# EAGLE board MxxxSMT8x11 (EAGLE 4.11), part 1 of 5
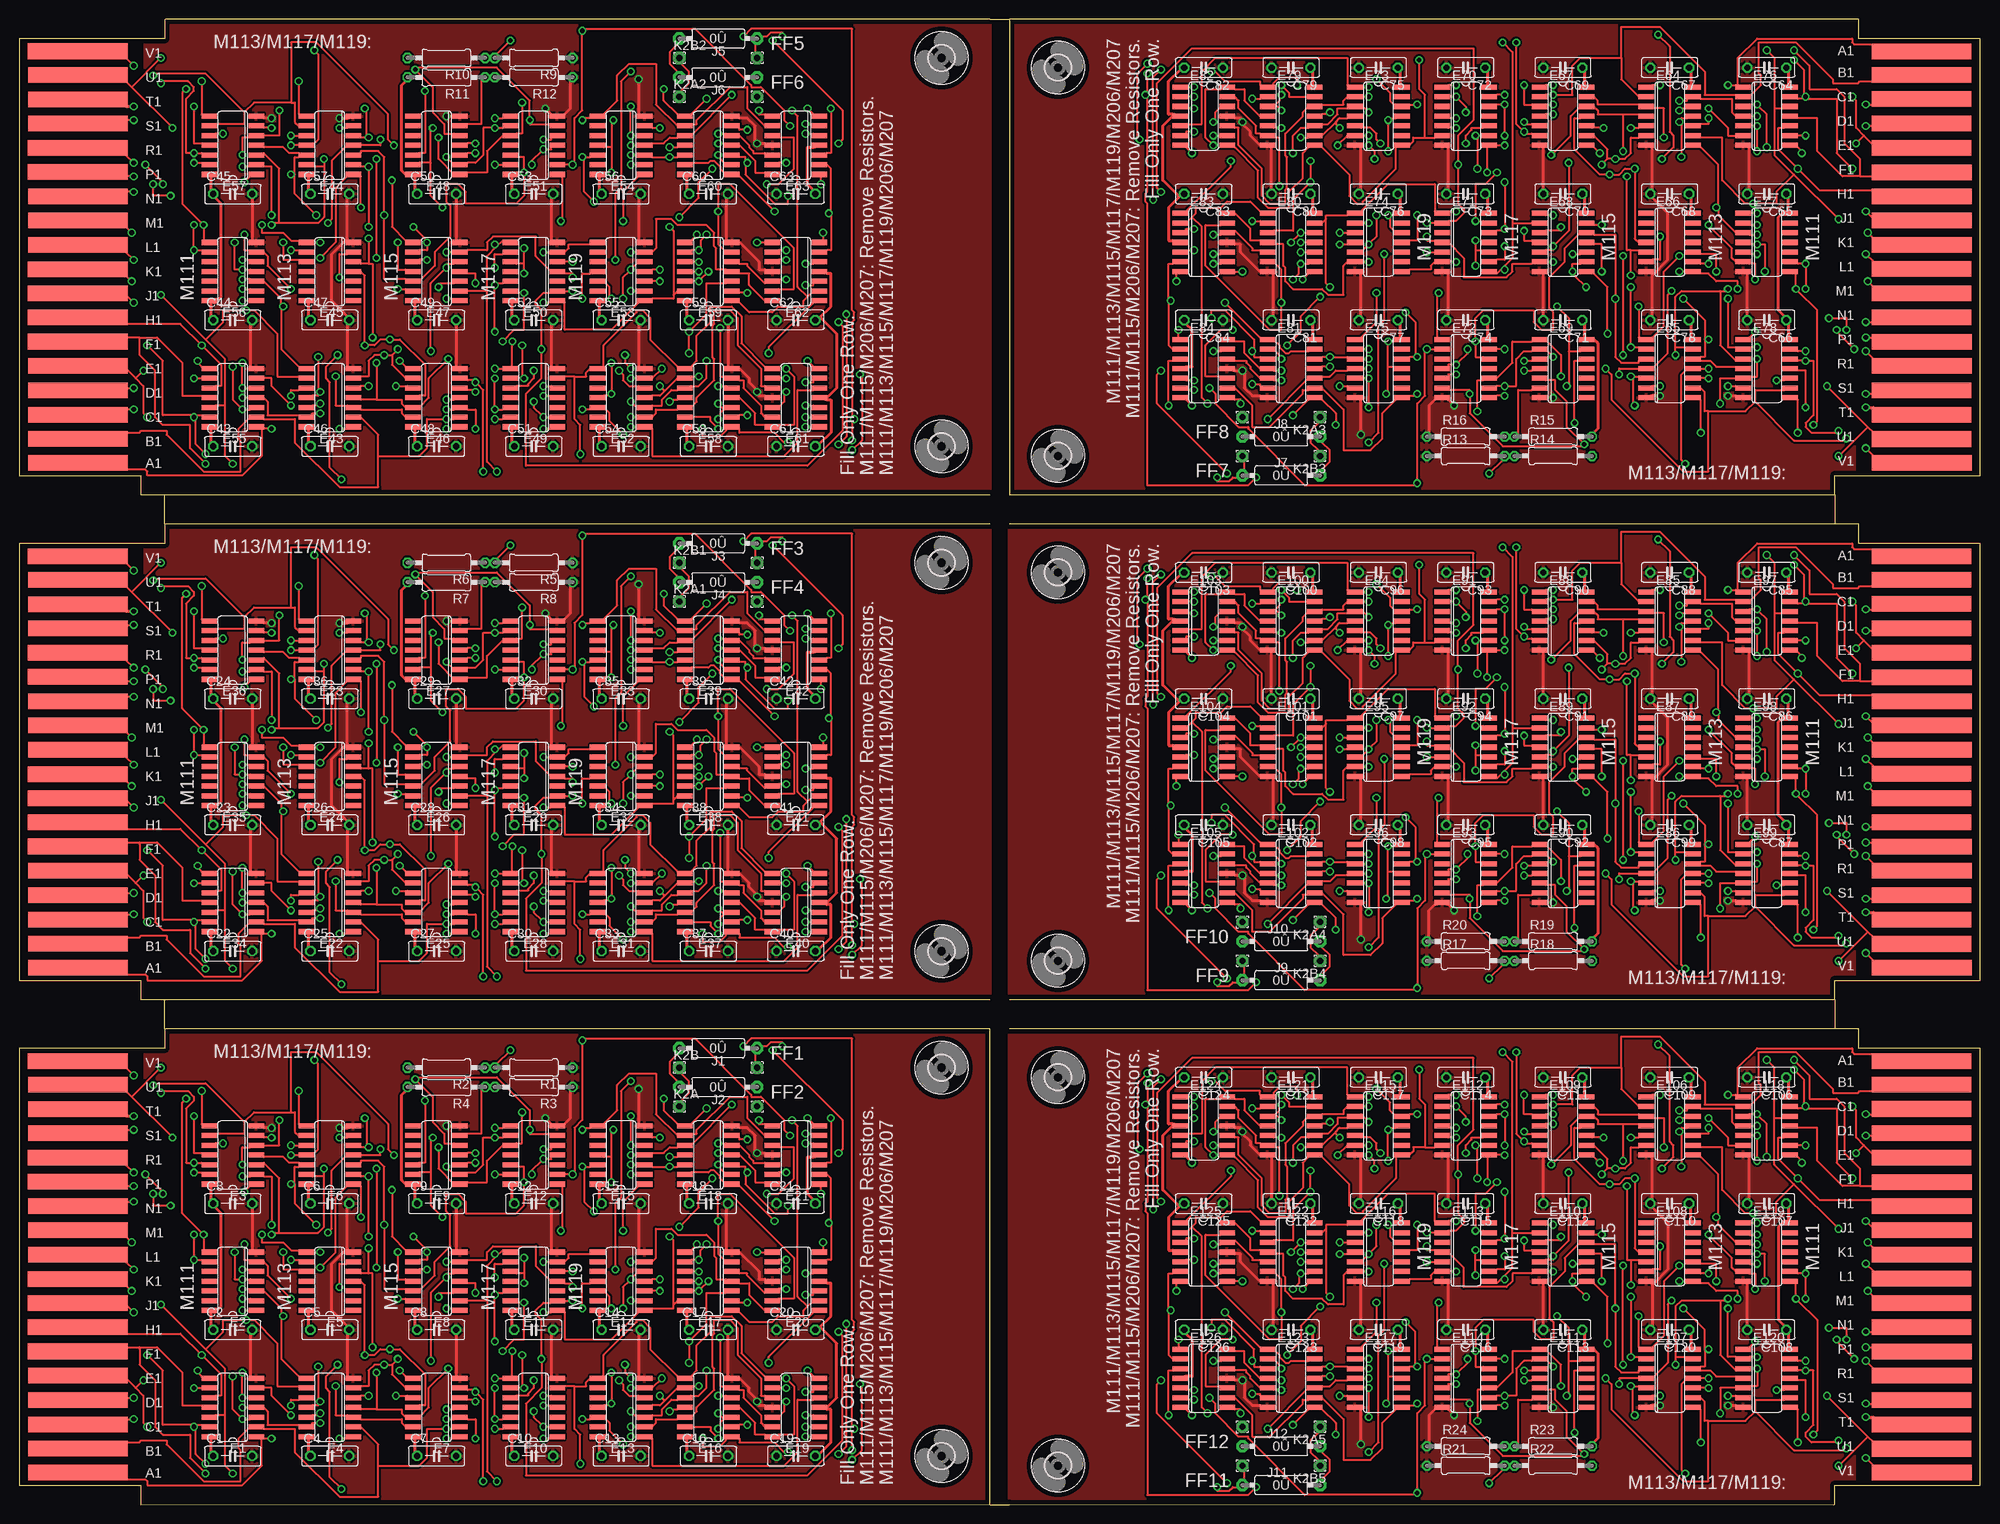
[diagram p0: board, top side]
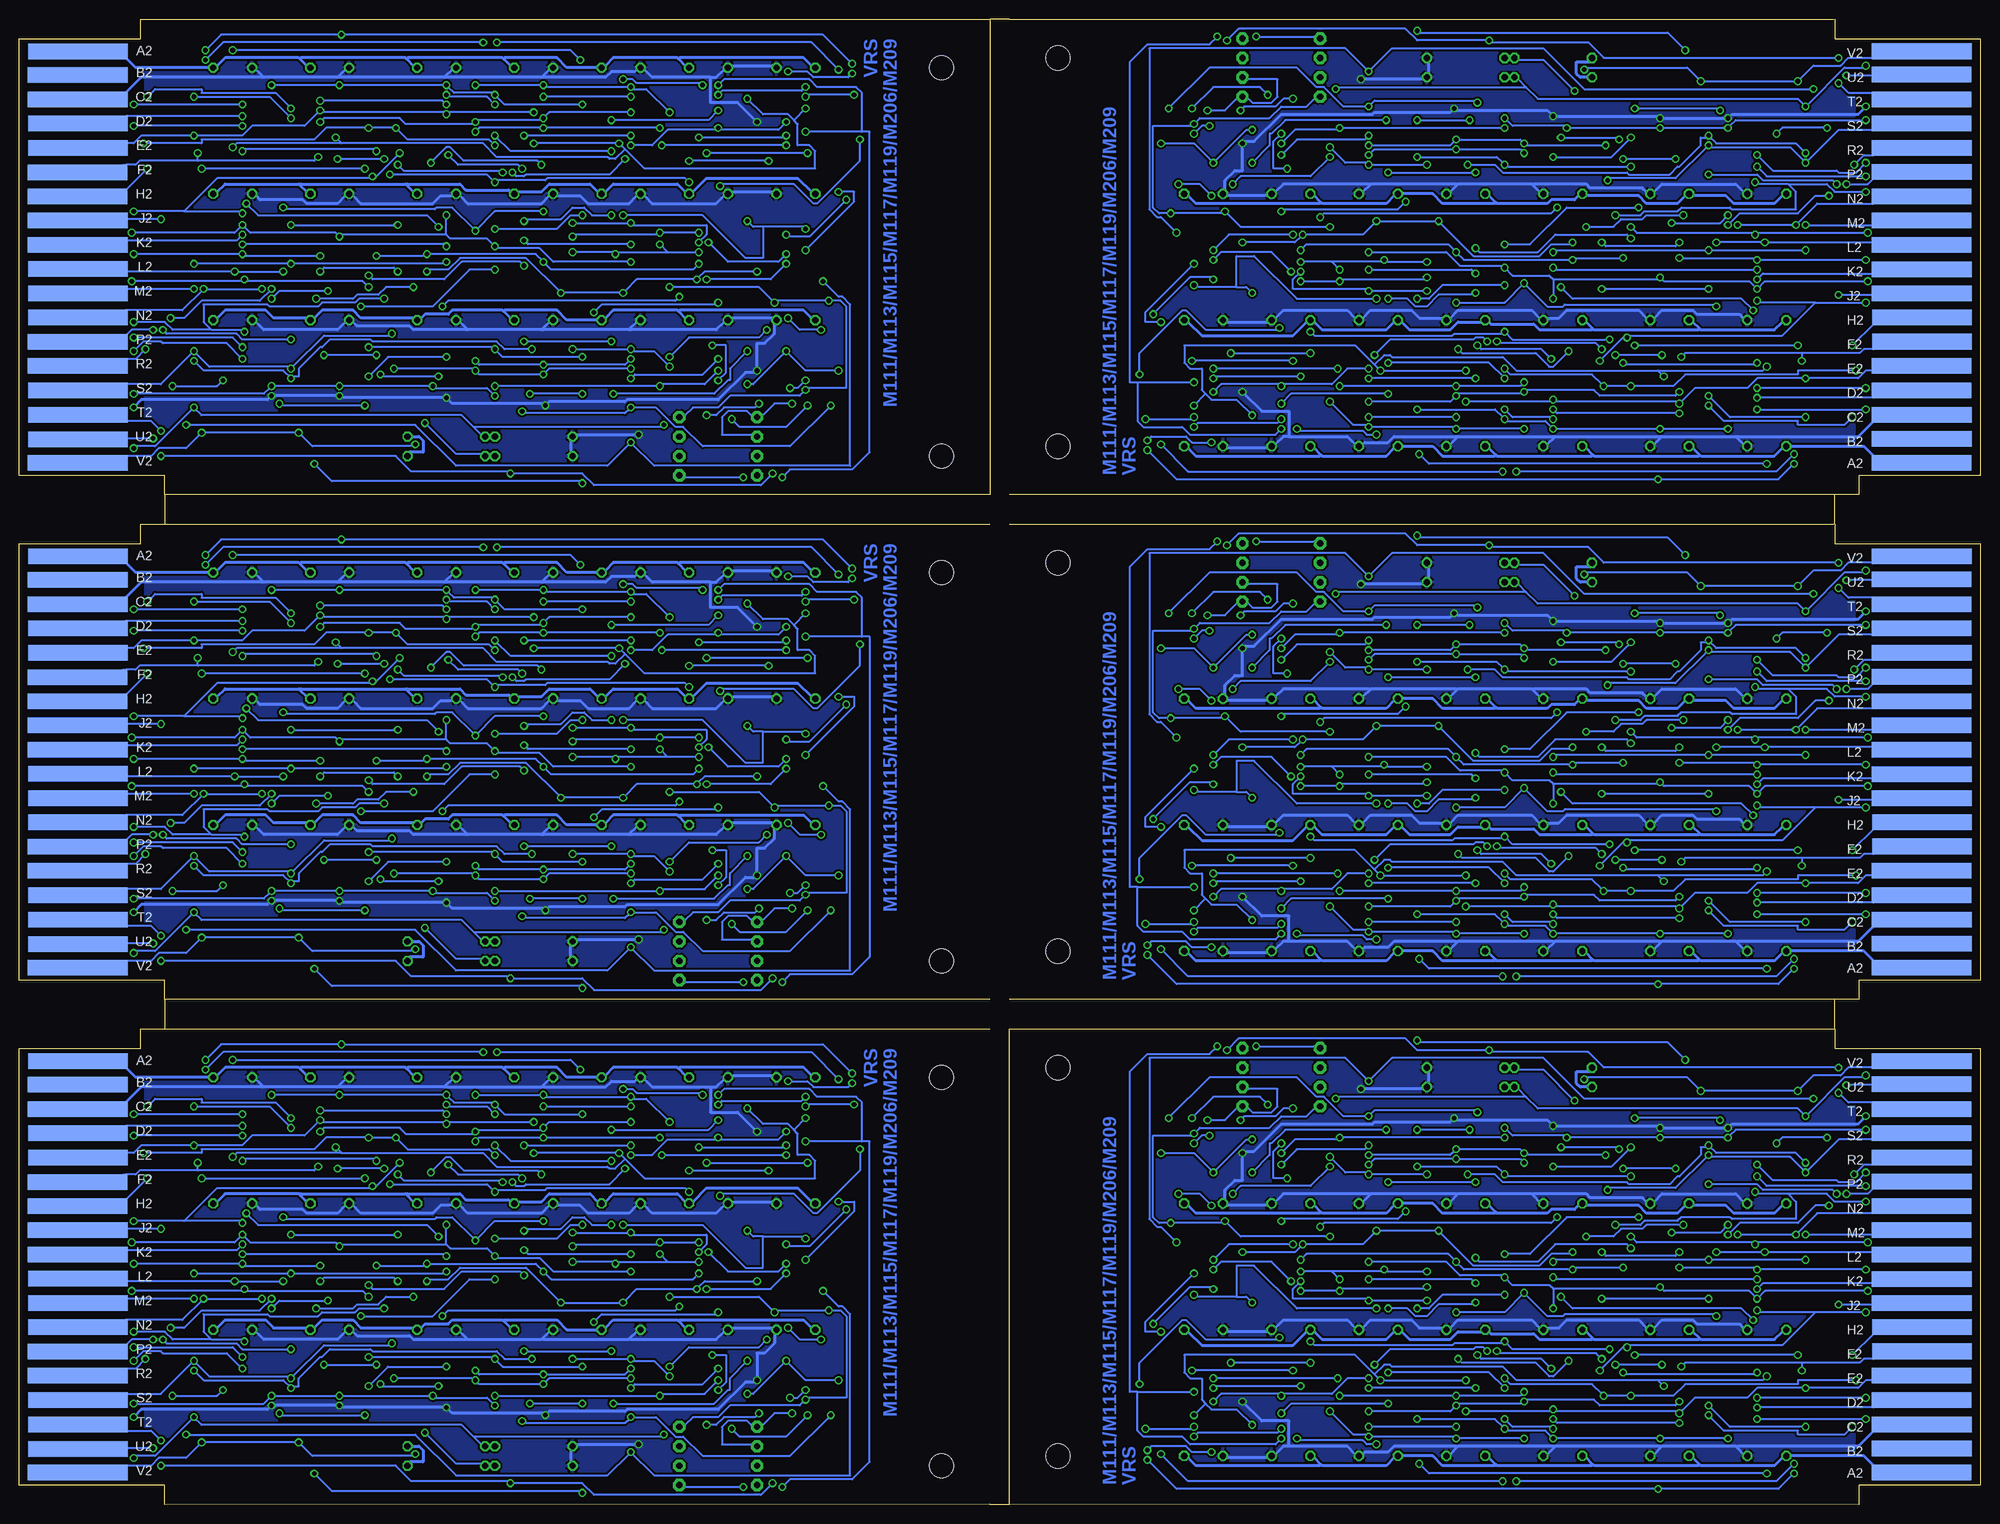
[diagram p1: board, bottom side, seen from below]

Size 256.54 x 194.31 mm. Coordinates in mm from the lower left corner, seen from the top.
Outline: 15.88,0 126.99,0.04 126.99,62.19 19.18,62.23
Outline: 15.88,66.04 126.99,66.08
Outline: 126.99,128.23 19.18,128.27
Outline: 15.88,132.08 126.99,132.12
Outline: 126.99,194.27 19.18,194.31
Outline: 240.67,194.31 129.56,194.27 129.56,132.12 237.36,132.08
Outline: 240.67,128.27 129.56,128.23
Outline: 129.56,66.08 237.36,66.04
Outline: 240.67,62.23 129.56,62.19
Outline: 129.56,0.04 237.36,0
Outline: 127,194.31 129.54,194.31
Outline: 127,0 129.54,0
Outline: 19.05,128.27 19.05,132.08
Outline: 19.05,62.23 19.05,66.04
Outline: 237.49,66.04 237.49,62.23
Outline: 237.49,132.08 237.49,128.27
Copper layers (1*16): Top 0.035mm / dielectric 1.5mm / Bottom 0.035mm
Design rules "olimex10mil": minimum track width 10mil, minimum drill 24mil, track to track 10mil, track to pad 10mil, pad to pad 10mil, via to via 10mil, smd to smd 10mil, copper to edge 25mil, drill to drill 10mil, minimum pad ring 10mil, minimum via ring 8mil, stop-mask expansion 0mil, vias tented up to drill 0mil, thermal gap 10mil
Net classes: 1 Power: width 0.381 mm

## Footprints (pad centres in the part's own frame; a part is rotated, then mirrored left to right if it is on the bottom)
C050-025X075 = drill 0.813 octagon: 1 -2.54,0; 2 2.54,0
SO14 = smd 0.66 x 2.032: 1 -3.81,-3.073; 2 -2.54,-3.073; 3 -1.27,-3.073; 4 0,-3.073; 5 1.27,-3.073; 6 2.54,-3.073; 7 3.81,-3.073; 8 3.81,3.073; 9 2.54,3.073; 10 1.27,3.073; 11 0,3.073; 12 -1.27,3.073; 13 -2.54,3.073; 14 -3.81,3.073
1,6/0,8 = drill 0.813 pad 1.6 octagon: 1 0,0
0R/10 = drill 0.813 pad 1.6 octagon: 1 -5.08,0; 2 5.08,0
0207/10 = drill 0.813 octagon: 1 -5.08,0; 2 5.08,0
EDGE-CON2 = smd 13.017 x 2.032: A1 7.709,4.207; B1 7.684,7.312; C1 7.684,10.474; D1 7.684,13.665; E1 7.693,16.84; F1 7.668,20.041; H1 7.668,23.19; J1 7.668,26.34; K1 7.668,29.515; L1 7.693,32.69; M1 7.693,35.89; N1 7.693,39.04; P1 7.668,42.24; R1 7.668,45.39; S1 7.693,48.565; T1 7.693,51.74; U1 7.693,54.94; V1 7.668,58.026 | smd 13.017 x 2.032 bottom: A2 7.69,4.207; B2 7.668,7.328; C2 7.668,10.49; D2 7.693,13.665; E2 7.693,16.84; F2 7.642,20.041; H2 7.642,23.19; J2 7.668,26.34; K2 7.668,29.515; L2 7.693,32.69; M2 7.693,35.89; N2 7.693,39.04; P2 7.668,42.24; R2 7.668,45.39; S2 7.693,48.565; T2 7.693,51.74; U2 7.693,54.966; V2 7.668,58.026
3,2 = hole 3.2: 0,0

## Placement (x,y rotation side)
C1  0.1uf  [C050-025X075]  27.94,6.35 0 top
C2  0.1uf  [C050-025X075]  27.94,22.86 0 top
C3  0.1uf  [C050-025X075]  27.94,39.37 0 top
C4  0.1uf  [C050-025X075]  40.64,6.35 0 top
C5  0.1uf  [C050-025X075]  40.64,22.86 0 top
C6  0.1uf  [C050-025X075]  40.64,39.37 0 top
C7  0.1uf  [C050-025X075]  54.61,6.35 0 top
C8  0.1uf  [C050-025X075]  54.61,22.86 0 top
C9  0.1uf  [C050-025X075]  54.61,39.37 0 top
C10  0.1uf  [C050-025X075]  67.31,6.35 0 top
C11  0.1uf  [C050-025X075]  67.31,22.86 0 top
C12  0.1uf  [C050-025X075]  67.31,39.37 0 top
C13  0.1uf  [C050-025X075]  78.74,6.35 0 top
C14  0.1uf  [C050-025X075]  78.74,22.86 0 top
C15  0.1uf  [C050-025X075]  78.74,39.37 0 top
C16  0.1uf  [C050-025X075]  90.17,6.35 0 top
C17  0.1uf  [C050-025X075]  90.17,22.86 0 top
C18  0.1uf  [C050-025X075]  90.17,39.37 0 top
C19  0.1uf  [C050-025X075]  101.6,6.35 180 top
C20  0.1uf  [C050-025X075]  101.6,22.86 180 top
C21  0.1uf  [C050-025X075]  101.6,39.37 180 top
C22  0.1uf  [C050-025X075]  27.94,72.39 0 top
C23  0.1uf  [C050-025X075]  27.94,88.9 0 top
C24  0.1uf  [C050-025X075]  27.94,105.41 0 top
C25  0.1uf  [C050-025X075]  40.64,72.39 0 top
C26  0.1uf  [C050-025X075]  40.64,88.9 0 top
C27  0.1uf  [C050-025X075]  54.61,72.39 0 top
C28  0.1uf  [C050-025X075]  54.61,88.9 0 top
C29  0.1uf  [C050-025X075]  54.61,105.41 0 top
C30  0.1uf  [C050-025X075]  67.31,72.39 0 top
C31  0.1uf  [C050-025X075]  67.31,88.9 0 top
C32  0.1uf  [C050-025X075]  67.31,105.41 0 top
C33  0.1uf  [C050-025X075]  78.74,72.39 0 top
C34  0.1uf  [C050-025X075]  78.74,88.9 0 top
C35  0.1uf  [C050-025X075]  78.74,105.41 0 top
C36  0.1uf  [C050-025X075]  40.64,105.41 0 top
C37  0.1uf  [C050-025X075]  90.17,72.39 0 top
C38  0.1uf  [C050-025X075]  90.17,88.9 0 top
C39  0.1uf  [C050-025X075]  90.17,105.41 0 top
C40  0.1uf  [C050-025X075]  101.6,72.39 180 top
C41  0.1uf  [C050-025X075]  101.6,88.9 180 top
C42  0.1uf  [C050-025X075]  101.6,105.41 180 top
C43  0.1uf  [C050-025X075]  27.94,138.43 0 top
C44  0.1uf  [C050-025X075]  27.94,154.94 0 top
C45  0.1uf  [C050-025X075]  27.94,171.45 0 top
C46  0.1uf  [C050-025X075]  40.64,138.43 0 top
C47  0.1uf  [C050-025X075]  40.64,154.94 0 top
C48  0.1uf  [C050-025X075]  54.61,138.43 0 top
C49  0.1uf  [C050-025X075]  54.61,154.94 0 top
C50  0.1uf  [C050-025X075]  54.61,171.45 0 top
C51  0.1uf  [C050-025X075]  67.31,138.43 0 top
C52  0.1uf  [C050-025X075]  67.31,154.94 0 top
C53  0.1uf  [C050-025X075]  67.31,171.45 0 top
C54  0.1uf  [C050-025X075]  78.74,138.43 0 top
C55  0.1uf  [C050-025X075]  78.74,154.94 0 top
C56  0.1uf  [C050-025X075]  78.74,171.45 0 top
C57  0.1uf  [C050-025X075]  40.64,171.45 0 top
C58  0.1uf  [C050-025X075]  90.17,138.43 0 top
C59  0.1uf  [C050-025X075]  90.17,154.94 0 top
C60  0.1uf  [C050-025X075]  90.17,171.45 0 top
C61  0.1uf  [C050-025X075]  101.6,138.43 180 top
C62  0.1uf  [C050-025X075]  101.6,154.94 180 top
C63  0.1uf  [C050-025X075]  101.6,171.45 180 top
C64  0.1uf  [C050-025X075]  228.6,187.96 180 top
C65  0.1uf  [C050-025X075]  228.6,171.45 180 top
C66  0.1uf  [C050-025X075]  228.6,154.94 180 top
C67  0.1uf  [C050-025X075]  215.9,187.96 180 top
C68  0.1uf  [C050-025X075]  215.9,171.45 180 top
C69  0.1uf  [C050-025X075]  201.93,187.96 180 top
C70  0.1uf  [C050-025X075]  201.93,171.45 180 top
C71  0.1uf  [C050-025X075]  201.93,154.94 180 top
C72  0.1uf  [C050-025X075]  189.23,187.96 180 top
C73  0.1uf  [C050-025X075]  189.23,171.45 180 top
C74  0.1uf  [C050-025X075]  189.23,154.94 180 top
C75  0.1uf  [C050-025X075]  177.8,187.96 180 top
C76  0.1uf  [C050-025X075]  177.8,171.45 180 top
C77  0.1uf  [C050-025X075]  177.8,154.94 180 top
C78  0.1uf  [C050-025X075]  215.9,154.94 180 top
C79  0.1uf  [C050-025X075]  166.37,187.96 180 top
C80  0.1uf  [C050-025X075]  166.37,171.45 180 top
C81  0.1uf  [C050-025X075]  166.37,154.94 180 top
C82  0.1uf  [C050-025X075]  154.94,187.96 0 top
C83  0.1uf  [C050-025X075]  154.94,171.45 0 top
C84  0.1uf  [C050-025X075]  154.94,154.94 0 top
C85  0.1uf  [C050-025X075]  228.6,121.92 180 top
C86  0.1uf  [C050-025X075]  228.6,105.41 180 top
C87  0.1uf  [C050-025X075]  228.6,88.9 180 top
C88  0.1uf  [C050-025X075]  215.9,121.92 180 top
C89  0.1uf  [C050-025X075]  215.9,105.41 180 top
C90  0.1uf  [C050-025X075]  201.93,121.92 180 top
C91  0.1uf  [C050-025X075]  201.93,105.41 180 top
C92  0.1uf  [C050-025X075]  201.93,88.9 180 top
C93  0.1uf  [C050-025X075]  189.23,121.92 180 top
C94  0.1uf  [C050-025X075]  189.23,105.41 180 top
C95  0.1uf  [C050-025X075]  189.23,88.9 180 top
C96  0.1uf  [C050-025X075]  177.8,121.92 180 top
C97  0.1uf  [C050-025X075]  177.8,105.41 180 top
C98  0.1uf  [C050-025X075]  177.8,88.9 180 top
C99  0.1uf  [C050-025X075]  215.9,88.9 180 top
C100  0.1uf  [C050-025X075]  166.37,121.92 180 top
C101  0.1uf  [C050-025X075]  166.37,105.41 180 top
C102  0.1uf  [C050-025X075]  166.37,88.9 180 top
C103  0.1uf  [C050-025X075]  154.94,121.92 0 top
C104  0.1uf  [C050-025X075]  154.94,105.41 0 top
C105  0.1uf  [C050-025X075]  154.94,88.9 0 top
C106  0.1uf  [C050-025X075]  228.6,55.88 180 top
C107  0.1uf  [C050-025X075]  228.6,39.37 180 top
C108  0.1uf  [C050-025X075]  228.6,22.86 180 top
C109  0.1uf  [C050-025X075]  215.9,55.88 180 top
C110  0.1uf  [C050-025X075]  215.9,39.37 180 top
C111  0.1uf  [C050-025X075]  201.93,55.88 180 top
C112  0.1uf  [C050-025X075]  201.93,39.37 180 top
C113  0.1uf  [C050-025X075]  201.93,22.86 180 top
C114  0.1uf  [C050-025X075]  189.23,55.88 180 top
C115  0.1uf  [C050-025X075]  189.23,39.37 180 top
C116  0.1uf  [C050-025X075]  189.23,22.86 180 top
C117  0.1uf  [C050-025X075]  177.8,55.88 180 top
C118  0.1uf  [C050-025X075]  177.8,39.37 180 top
C119  0.1uf  [C050-025X075]  177.8,22.86 180 top
C120  0.1uf  [C050-025X075]  215.9,22.86 180 top
C121  0.1uf  [C050-025X075]  166.37,55.88 180 top
C122  0.1uf  [C050-025X075]  166.37,39.37 180 top
C123  0.1uf  [C050-025X075]  166.37,22.86 180 top
C124  0.1uf  [C050-025X075]  154.94,55.88 0 top
C125  0.1uf  [C050-025X075]  154.94,39.37 0 top
C126  0.1uf  [C050-025X075]  154.94,22.86 0 top
E1  7404D  [SO14]  27.94,12.7 90 top
E2  7404D  [SO14]  27.94,29.21 90 top
E3  7404D  [SO14]  27.94,45.72 90 top
E4  7400D  [SO14]  40.64,12.7 90 top
E5  7400D  [SO14]  40.64,29.21 90 top
E6  7400D  [SO14]  40.64,45.72 90 top
E7  7410D  [SO14]  54.61,12.7 90 top
E8  7410D  [SO14]  54.61,29.21 90 top
E9  7410D  [SO14]  54.61,45.72 90 top
E10  7420D  [SO14]  67.31,12.7 90 top
E11  7420D  [SO14]  67.31,29.21 90 top
E12  7420D  [SO14]  67.31,45.72 90 top
E13  7430D  [SO14]  78.74,12.7 90 top
E14  7430D  [SO14]  78.74,29.21 90 top
E15  7430D  [SO14]  78.74,45.72 90 top
E16  7474D  [SO14]  90.17,12.7 90 top
E17  7474D  [SO14]  90.17,29.21 90 top
E18  7474D  [SO14]  90.17,45.72 90 top
E19  7473D  [SO14]  101.6,12.7 90 top
E20  7473D  [SO14]  101.6,29.21 90 top
E21  7473D  [SO14]  101.6,45.72 90 top
E22  7400D  [SO14]  40.64,78.74 90 top
E23  7400D  [SO14]  40.64,111.76 90 top
E24  7400D  [SO14]  40.64,95.25 90 top
E25  7410D  [SO14]  54.61,78.74 90 top
E26  7410D  [SO14]  54.61,95.25 90 top
E27  7410D  [SO14]  54.61,111.76 90 top
E28  7420D  [SO14]  67.31,78.74 90 top
E29  7420D  [SO14]  67.31,95.25 90 top
E30  7420D  [SO14]  67.31,111.76 90 top
E31  7430D  [SO14]  78.74,78.74 90 top
E32  7430D  [SO14]  78.74,95.25 90 top
E33  7430D  [SO14]  78.74,111.76 90 top
E34  7404D  [SO14]  27.94,78.74 90 top
E35  7404D  [SO14]  27.94,95.25 90 top
E36  7404D  [SO14]  27.94,111.76 90 top
E37  7474D  [SO14]  90.17,78.74 90 top
E38  7474D  [SO14]  90.17,95.25 90 top
E39  7474D  [SO14]  90.17,111.76 90 top
E40  7473D  [SO14]  101.6,78.74 90 top
E41  7473D  [SO14]  101.6,95.25 90 top
E42  7473D  [SO14]  101.6,111.76 90 top
E43  7400D  [SO14]  40.64,144.78 90 top
E44  7400D  [SO14]  40.64,177.8 90 top
E45  7400D  [SO14]  40.64,161.29 90 top
E46  7410D  [SO14]  54.61,144.78 90 top
E47  7410D  [SO14]  54.61,161.29 90 top
E48  7410D  [SO14]  54.61,177.8 90 top
E49  7420D  [SO14]  67.31,144.78 90 top
E50  7420D  [SO14]  67.31,161.29 90 top
E51  7420D  [SO14]  67.31,177.8 90 top
E52  7430D  [SO14]  78.74,144.78 90 top
E53  7430D  [SO14]  78.74,161.29 90 top
E54  7430D  [SO14]  78.74,177.8 90 top
E55  7404D  [SO14]  27.94,144.78 90 top
E56  7404D  [SO14]  27.94,161.29 90 top
E57  7404D  [SO14]  27.94,177.8 90 top
E58  7474D  [SO14]  90.17,144.78 90 top
E59  7474D  [SO14]  90.17,161.29 90 top
E60  7474D  [SO14]  90.17,177.8 90 top
E61  7473D  [SO14]  101.6,144.78 90 top
E62  7473D  [SO14]  101.6,161.29 90 top
E63  7473D  [SO14]  101.6,177.8 90 top
E64  7400D  [SO14]  215.9,181.61 270 top
E65  7400D  [SO14]  215.9,148.59 270 top
E66  7400D  [SO14]  215.9,165.1 270 top
E67  7410D  [SO14]  201.93,181.61 270 top
E68  7410D  [SO14]  201.93,165.1 270 top
E69  7410D  [SO14]  201.93,148.59 270 top
E70  7420D  [SO14]  189.23,181.61 270 top
E71  7420D  [SO14]  189.23,165.1 270 top
E72  7420D  [SO14]  189.23,148.59 270 top
E73  7430D  [SO14]  177.8,181.61 270 top
E74  7430D  [SO14]  177.8,165.1 270 top
E75  7430D  [SO14]  177.8,148.59 270 top
E76  7404D  [SO14]  228.6,181.61 270 top
E77  7404D  [SO14]  228.6,165.1 270 top
E78  7404D  [SO14]  228.6,148.59 270 top
E79  7474D  [SO14]  166.37,181.61 270 top
E80  7474D  [SO14]  166.37,165.1 270 top
E81  7474D  [SO14]  166.37,148.59 270 top
E82  7473D  [SO14]  154.94,181.61 270 top
E83  7473D  [SO14]  154.94,165.1 270 top
E84  7473D  [SO14]  154.94,148.59 270 top
E85  7400D  [SO14]  215.9,115.57 270 top
E86  7400D  [SO14]  215.9,82.55 270 top
E87  7400D  [SO14]  215.9,99.06 270 top
E88  7410D  [SO14]  201.93,115.57 270 top
E89  7410D  [SO14]  201.93,99.06 270 top
E90  7410D  [SO14]  201.93,82.55 270 top
E91  7420D  [SO14]  189.23,115.57 270 top
E92  7420D  [SO14]  189.23,99.06 270 top
E93  7420D  [SO14]  189.23,82.55 270 top
E94  7430D  [SO14]  177.8,115.57 270 top
E95  7430D  [SO14]  177.8,99.06 270 top
E96  7430D  [SO14]  177.8,82.55 270 top
E97  7404D  [SO14]  228.6,115.57 270 top
E98  7404D  [SO14]  228.6,99.06 270 top
E99  7404D  [SO14]  228.6,82.55 270 top
E100  7474D  [SO14]  166.37,115.57 270 top
E101  7474D  [SO14]  166.37,99.06 270 top
E102  7474D  [SO14]  166.37,82.55 270 top
E103  7473D  [SO14]  154.94,115.57 270 top
E104  7473D  [SO14]  154.94,99.06 270 top
E105  7473D  [SO14]  154.94,82.55 270 top
E106  7400D  [SO14]  215.9,49.53 270 top
E107  7400D  [SO14]  215.9,16.51 270 top
E108  7400D  [SO14]  215.9,33.02 270 top
E109  7410D  [SO14]  201.93,49.53 270 top
E110  7410D  [SO14]  201.93,33.02 270 top
E111  7410D  [SO14]  201.93,16.51 270 top
E112  7420D  [SO14]  189.23,49.53 270 top
E113  7420D  [SO14]  189.23,33.02 270 top
E114  7420D  [SO14]  189.23,16.51 270 top
E115  7430D  [SO14]  177.8,49.53 270 top
E116  7430D  [SO14]  177.8,33.02 270 top
E117  7430D  [SO14]  177.8,16.51 270 top
E118  7404D  [SO14]  228.6,49.53 270 top
E119  7404D  [SO14]  228.6,33.02 270 top
E120  7404D  [SO14]  228.6,16.51 270 top
E121  7474D  [SO14]  166.37,49.53 270 top
E122  7474D  [SO14]  166.37,33.02 270 top
E123  7474D  [SO14]  166.37,16.51 270 top
E124  7473D  [SO14]  154.94,49.53 270 top
E125  7473D  [SO14]  154.94,33.02 270 top
E126  7473D  [SO14]  154.94,16.51 270 top
FF1  [1,6/0,8]  96.52,57.15 0 top
FF2  [1,6/0,8]  96.52,52.07 0 top
FF3  [1,6/0,8]  96.52,123.19 0 top
FF4  [1,6/0,8]  96.52,118.11 0 top
FF5  [1,6/0,8]  96.52,189.23 0 top
FF6  [1,6/0,8]  96.52,184.15 0 top
FF7  [1,6/0,8]  160.02,137.16 180 top
FF8  [1,6/0,8]  160.02,142.24 180 top
FF9  [1,6/0,8]  160.02,71.12 180 top
FF10  [1,6/0,8]  160.02,76.2 180 top
FF11  [1,6/0,8]  160.02,5.08 180 top
FF12  [1,6/0,8]  160.02,10.16 180 top
J1  [0R/10]  91.44,59.69 0 top
J2  [0R/10]  91.44,54.61 0 top
J3  [0R/10]  91.44,125.73 0 top
J4  [0R/10]  91.44,120.65 0 top
J5  [0R/10]  91.44,191.77 0 top
J6  [0R/10]  91.44,186.69 0 top
J7  [0R/10]  165.1,134.62 180 top
J8  [0R/10]  165.1,139.7 180 top
J9  [0R/10]  165.1,68.58 180 top
J10  [0R/10]  165.1,73.66 180 top
J11  [0R/10]  165.1,2.54 180 top
J12  [0R/10]  165.1,7.62 180 top
K2A  [1,6/0,8]  86.36,52.07 0 top
K2A1  [1,6/0,8]  86.36,118.11 0 top
K2A2  [1,6/0,8]  86.36,184.15 0 top
K2A3  [1,6/0,8]  170.18,142.24 180 top
K2A4  [1,6/0,8]  170.18,76.2 180 top
K2A5  [1,6/0,8]  170.18,10.16 180 top
K2B  [1,6/0,8]  86.36,57.15 0 top
K2B1  [1,6/0,8]  86.36,123.19 0 top
K2B2  [1,6/0,8]  86.36,189.23 0 top
K2B3  [1,6/0,8]  170.18,137.16 180 top
K2B4  [1,6/0,8]  170.18,71.12 180 top
K2B5  [1,6/0,8]  170.18,5.08 180 top
R1  750  [0207/10]  67.31,57.15 180 top
R2  330  [0207/10]  55.88,57.15 180 top
R3  750  [0207/10]  67.31,54.61 180 top
R4  330  [0207/10]  55.88,54.61 180 top
R5  750  [0207/10]  67.31,123.19 180 top
R6  330  [0207/10]  55.88,123.19 180 top
R7  330  [0207/10]  55.88,120.65 180 top
R8  750  [0207/10]  67.31,120.65 180 top
R9  750  [0207/10]  67.31,189.23 180 top
R10  330  [0207/10]  55.88,189.23 180 top
R11  330  [0207/10]  55.88,186.69 180 top
R12  750  [0207/10]  67.31,186.69 180 top
R13  750  [0207/10]  189.23,137.16 0 top
R14  330  [0207/10]  200.66,137.16 0 top
R15  330  [0207/10]  200.66,139.7 0 top
R16  750  [0207/10]  189.23,139.7 0 top
R17  750  [0207/10]  189.23,71.12 0 top
R18  330  [0207/10]  200.66,71.12 0 top
R19  330  [0207/10]  200.66,73.66 0 top
R20  750  [0207/10]  189.23,73.66 0 top
R21  750  [0207/10]  189.23,5.08 0 top
R22  330  [0207/10]  200.66,5.08 0 top
R23  330  [0207/10]  200.66,7.62 0 top
R24  750  [0207/10]  189.23,7.62 0 top
U$1  [EDGE-CON2]  0,0 0 top
U$2  [3,2]  120.65,6.35 0 top
U$3  [3,2]  120.65,57.15 0 top
U$4  [3,2]  120.65,72.39 0 top
U$5  [3,2]  120.65,123.19 0 top
U$6  [EDGE-CON2]  0,66.04 0 top
U$7  [3,2]  120.65,138.43 0 top
U$8  [3,2]  120.65,189.23 0 top
U$9  [EDGE-CON2]  0,132.08 0 top
U$10  [3,2]  135.89,187.96 180 top
U$11  [3,2]  135.89,137.16 180 top
U$12  [EDGE-CON2]  256.54,194.31 180 top
U$13  [3,2]  135.89,121.92 180 top
U$14  [3,2]  135.89,71.12 180 top
U$15  [EDGE-CON2]  256.54,128.27 180 top
U$16  [3,2]  135.89,55.88 180 top
U$17  [3,2]  135.89,5.08 180 top
U$18  [EDGE-CON2]  256.54,62.23 180 top

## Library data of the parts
C1-C126 R1-R24 = rcl
E1-E126 = 74xx-us
FF1-FF12 K2A K2A1-K2A5 K2B K2B1-K2B5 = wirepad
J1-J12 = jumper
U$1 U$6 U$9 U$12 U$15 U$18 = dec-con
U$2-U$5 U$7 U$8 U$10 U$11 U$13 U$14 U$16 U$17 = holes

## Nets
A1: E1.1 E4.1 E7.1 E10.13 E13.12 E16.1 E19.2 J1.1 J2.1 U$1.A1
A2: E22.1 E25.1 E28.13 E31.12 E34.1 E37.1 E40.2 J3.1 J4.1 U$6.A1
A3: E43.1 E46.1 E49.13 E52.12 E55.1 E58.1 E61.2 J5.1 J6.1 U$9.A1
A4: E64.1 E67.1 E70.13 E73.12 E76.1 E79.1 E82.2 J7.1 J8.1 U$12.A1
A5: E85.1 E88.1 E91.13 E94.12 E97.1 E100.1 E103.2 J9.1 J10.1 U$15.A1
A6: E106.1 E109.1 E112.13 E115.12 E118.1 E121.1 E124.2 J11.1 J12.1 U$18.A1
B1: E1.2 E4.2 E7.2 E10.12 E13.11 E16.3 E19.1 U$1.B1
B2: U$1.B2
B3: U$6.B2
B4: E22.2 E25.2 E28.12 E31.11 E34.2 E37.3 E40.1 U$6.B1
B5: U$9.B2
B6: E43.2 E46.2 E49.12 E52.11 E55.2 E58.3 E61.1 U$9.B1
B7: U$12.B2
B8: E64.2 E67.2 E70.12 E73.11 E76.2 E79.3 E82.1 U$12.B1
B9: U$15.B2
B10: E85.2 E88.2 E91.12 E94.11 E97.2 E100.3 E103.1 U$15.B1
B11: U$18.B2
B12: E106.2 E109.2 E112.12 E115.11 E118.2 E121.3 E124.1 U$18.B1
C1: E1.3 E4.3 E7.13 E10.10 E13.5 E16.2 E19.3 U$1.C1
C2: E22.3 E25.13 E28.10 E31.5 E34.3 E37.2 E40.3 U$6.C1
C3: E43.3 E46.13 E49.10 E52.5 E55.3 E58.2 E61.3 U$9.C1
C4: E64.3 E67.13 E70.10 E73.5 E76.3 E79.2 E82.3 U$12.C1
C5: E85.3 E88.13 E91.10 E94.5 E97.3 E100.2 E103.3 U$15.C1
C6: E106.3 E109.13 E112.10 E115.5 E118.3 E121.2 E124.3 U$18.C1
D1: E1.5 E4.4 E7.12 E10.9 E13.6 E16.4 E19.14 U$1.D1
D2: E1.4 E4.13 E7.3 E10.1 E13.1 E16.11 E19.5 U$1.D2
D3: E22.13 E25.3 E28.1 E31.1 E34.4 E37.11 E40.5 U$6.D2
D4: E22.4 E25.12 E28.9 E31.6 E34.5 E37.4 E40.14 U$6.D1
D5: E43.13 E46.3 E49.1 E52.1 E55.4 E58.11 E61.5 U$9.D2
D6: E43.4 E46.12 E49.9 E52.6 E55.5 E58.4 E61.14 U$9.D1
D7: E64.13 E67.3 E70.1 E73.1 E76.4 E79.11 E82.5 U$12.D2
D8: E64.4 E67.12 E70.9 E73.6 E76.5 E79.4 E82.14 U$12.D1
D9: E85.13 E88.3 E91.1 E94.1 E97.4 E100.11 E103.5 U$15.D2
D10: E85.4 E88.12 E91.9 E94.6 E97.5 E100.4 E103.14 U$15.D1
D11: E106.13 E109.3 E112.1 E115.1 E118.4 E121.11 E124.5 U$18.D2
D12: E106.4 E109.12 E112.9 E115.6 E118.5 E121.4 E124.14 U$18.D1
E1: E1.6 E4.5 E7.10 E10.8 E16.5 E19.12 U$1.E1
E2: E1.9 E4.12 E7.4 E10.2 E13.2 E16.12 E19.10 U$1.E2
E3: E22.12 E25.4 E28.2 E31.2 E34.9 E37.12 E40.10 U$6.E2
E4: E22.5 E25.10 E28.8 E34.6 E37.5 E40.12 U$6.E1
E5: E43.12 E46.4 E49.2 E52.2 E55.9 E58.12 E61.10 U$9.E2
E6: E43.5 E46.10 E49.8 E55.6 E58.5 E61.12 U$9.E1
E7: E64.12 E67.4 E70.2 E73.2 E76.9 E79.12 E82.10 U$12.E2
E8: E64.5 E67.10 E70.8 E76.6 E79.5 E82.12 U$12.E1
E9: E85.12 E88.4 E91.2 E94.2 E97.9 E100.12 E103.10 U$15.E2
E10: E85.5 E88.10 E91.8 E97.6 E100.5 E103.12 U$15.E1
E11: E106.12 E109.4 E112.2 E115.2 E118.9 E121.12 E124.10 U$18.E2
E12: E106.5 E109.10 E112.8 E118.6 E121.5 E124.12 U$18.E1
F1: E1.11 E4.6 E7.9 E11.13 E14.12 E16.6 E19.13 U$1.F1
F2: E1.8 E4.11 E7.5 E10.4 E13.3 E16.10 E19.7 U$1.F2
F3: E22.11 E25.5 E28.4 E31.3 E34.8 E37.10 E40.7 U$6.F2
F4: E22.6 E25.9 E29.13 E32.12 E34.11 E37.6 E40.13 U$6.F1
F5: E43.11 E46.5 E49.4 E52.3 E55.8 E58.10 E61.7 U$9.F2
F6: E43.6 E46.9 E50.13 E53.12 E55.11 E58.6 E61.13 U$9.F1
F7: E64.11 E67.5 E70.4 E73.3 E76.8 E79.10 E82.7 U$12.F2
F8: E64.6 E67.9 E71.13 E74.12 E76.11 E79.6 E82.13 U$12.F1
F9: E85.11 E88.5 E91.4 E94.3 E97.8 E100.10 E103.7 U$15.F2
F10: E85.6 E88.9 E92.13 E95.12 E97.11 E100.6 E103.13 U$15.F1
F11: E106.11 E109.5 E112.4 E115.3 E118.8 E121.10 E124.7 U$18.F2
F12: E106.6 E109.9 E113.13 E116.12 E118.11 E121.6 E124.13 U$18.F1
FF1: E16.13 E19.6 FF1.1 J1.2
FF2: E17.1 E20.2 FF2.1 J2.2
FF3: E37.13 E40.6 FF3.1 J3.2
FF4: E38.1 E41.2 FF4.1 J4.2
FF5: E58.13 E61.6 FF5.1 J5.2
FF6: E59.1 E62.2 FF6.1 J6.2
FF7: E79.13 E82.6 FF7.1 J7.2
FF8: E80.1 E83.2 FF8.1 J8.2
FF9: E100.13 E103.6 FF9.1 J9.2
FF10: E101.1 E104.2 FF10.1 J10.2
FF11: E121.13 E124.6 FF11.1 J11.2
FF12: E122.1 E125.2 FF12.1 J12.2
GND [Power]: C1.2 C2.2 C3.2 C4.2 C5.2 C6.2 C7.2 C8.2 C9.2 C10.2 C11.2 C12.2 C13.2 C14.2 C15.2 C16.2 C17.2 C18.2 C19.2 C20.2 C21.2 E1.7 E2.7 E3.7 E4.7 E5.7 E6.7 E7.7 E8.7 E9.7 E10.7 E11.7 E12.7 E13.7 E14.7 E15.7 E16.7 E17.7 E18.7 E19.11 E20.11 E21.11 R1.1 R3.1 U$1.C2 U$1.T1
GND1 [Power]: C22.2 C23.2 C24.2 C25.2 C26.2 C27.2 C28.2 C29.2 C30.2 C31.2 C32.2 C33.2 C34.2 C35.2 C36.2 C37.2 C38.2 C39.2 C40.2 C41.2 C42.2 E22.7 E23.7 E24.7 E25.7 E26.7 E27.7 E28.7 E29.7 E30.7 E31.7 E32.7 E33.7 E34.7 E35.7 E36.7 E37.7 E38.7 E39.7 E40.11 E41.11 E42.11 R5.1 R8.1 U$6.C2 U$6.T1
GND2 [Power]: C43.2 C44.2 C45.2 C46.2 C47.2 C48.2 C49.2 C50.2 C51.2 C52.2 C53.2 C54.2 C55.2 C56.2 C57.2 C58.2 C59.2 C60.2 C61.2 C62.2 C63.2 E43.7 E44.7 E45.7 E46.7 E47.7 E48.7 E49.7 E50.7 E51.7 E52.7 E53.7 E54.7 E55.7 E56.7 E57.7 E58.7 E59.7 E60.7 E61.11 E62.11 E63.11 R9.1 R12.1 U$9.C2 U$9.T1
GND3 [Power]: C64.2 C65.2 C66.2 C67.2 C68.2 C69.2 C70.2 C71.2 C72.2 C73.2 C74.2 C75.2 C76.2 C77.2 C78.2 C79.2 C80.2 C81.2 C82.2 C83.2 C84.2 E64.7 E65.7 E66.7 E67.7 E68.7 E69.7 E70.7 E71.7 E72.7 E73.7 E74.7 E75.7 E76.7 E77.7 E78.7 E79.7 E80.7 E81.7 E82.11 E83.11 E84.11 R13.1 R16.1 U$12.C2 U$12.T1
GND4 [Power]: C85.2 C86.2 C87.2 C88.2 C89.2 C90.2 C91.2 C92.2 C93.2 C94.2 C95.2 C96.2 C97.2 C98.2 C99.2 C100.2 C101.2 C102.2 C103.2 C104.2 C105.2 E85.7 E86.7 E87.7 E88.7 E89.7 E90.7 E91.7 E92.7 E93.7 E94.7 E95.7 E96.7 E97.7 E98.7 E99.7 E100.7 E101.7 E102.7 E103.11 E104.11 E105.11 R17.1 R20.1 U$15.C2 U$15.T1
GND5 [Power]: C106.2 C107.2 C108.2 C109.2 C110.2 C111.2 C112.2 C113.2 C114.2 C115.2 C116.2 C117.2 C118.2 C119.2 C120.2 C121.2 C122.2 C123.2 C124.2 C125.2 C126.2 E106.7 E107.7 E108.7 E109.7 E110.7 E111.7 E112.7 E113.7 E114.7 E115.7 E116.7 E117.7 E118.7 E119.7 E120.7 E121.7 E122.7 E123.7 E124.11 E125.11 E126.11 R21.1 R24.1 U$18.C2 U$18.T1
H1: E1.10 E5.4 E7.11 E11.12 E14.11 E17.3 E20.1 U$1.H1
H2: E1.13 E4.10 E7.6 E10.5 E13.4 E16.9 E19.9 U$1.H2
H3: E22.10 E25.6 E28.5 E31.4 E34.13 E37.9 E40.9 U$6.H2
H4: E24.4 E25.11 E29.12 E32.11 E34.10 E38.3 E41.1 U$6.H1
H5: E43.10 E46.6 E49.5 E52.4 E55.13 E58.9 E61.9 U$9.H2
H6: E45.4 E46.11 E50.12 E53.11 E55.10 E59.3 E62.1 U$9.H1
H7: E64.10 E67.6 E70.5 E73.4 E76.13 E79.9 E82.9 U$12.H2
H8: E66.4 E67.11 E71.12 E74.11 E76.10 E80.3 E83.1 U$12.H1
H9: E85.10 E88.6 E91.5 E94.4 E97.13 E100.9 E103.9 U$15.H2
H10: E87.4 E88.11 E92.12 E95.11 E97.10 E101.3 E104.1 U$15.H1
H11: E106.10 E109.6 E112.5 E115.4 E118.13 E121.9 E124.9 U$18.H2
H12: E108.4 E109.11 E113.12 E116.11 E118.10 E122.3 E125.1 U$18.H1
J1: E2.1 E5.5 E7.8 E11.10 E14.5 E17.2 E20.3 U$1.J1
J2: E1.12 E4.9 E8.3 E10.6 E13.8 E16.8 E19.8 U$1.J2
J3: E22.9 E26.3 E28.6 E31.8 E34.12 E37.8 E40.8 U$6.J2
J4: E24.5 E25.8 E29.10 E32.5 E35.1 E38.2 E41.3 U$6.J1
J5: E43.9 E47.3 E49.6 E52.8 E55.12 E58.8 E61.8 U$9.J2
J6: E45.5 E46.8 E50.10 E53.5 E56.1 E59.2 E62.3 U$9.J1
J7: E64.9 E68.3 E70.6 E73.8 E76.12 E79.8 E82.8 U$12.J2
J8: E66.5 E67.8 E71.10 E74.5 E77.1 E80.2 E83.3 U$12.J1
J9: E85.9 E89.3 E91.6 E94.8 E97.12 E100.8 E103.8 U$15.J2
J10: E87.5 E88.8 E92.10 E95.5 E98.1 E101.2 E104.3 U$15.J1
J11: E106.9 E110.3 E112.6 E115.8 E118.12 E121.8 E124.8 U$18.J2
J12: E108.5 E109.8 E113.10 E116.5 E119.1 E122.2 E125.3 U$18.J1
K1: E2.2 E5.6 E8.1 E11.9 E14.6 E17.4 E20.14 U$1.K1
K2: E2.3 E4.8 E8.4 E11.1 E14.1 E17.13 E18.1 E18.13 E20.6 E21.2 E21.6 K2A.1 K2B.1 U$1.K2
K3: E22.8 E26.4 E29.1 E32.1 E35.3 E38.13 E39.1 E39.13 E41.6 E42.2 E42.6 K2A1.1 K2B1.1 U$6.K2
K4: E24.6 E26.1 E29.9 E32.6 E35.2 E38.4 E41.14 U$6.K1
K5: E43.8 E47.4 E50.1 E53.1 E56.3 E59.13 E60.1 E60.13 E62.6 E63.2 E63.6 K2A2.1 K2B2.1 U$9.K2
K6: E45.6 E47.1 E50.9 E53.6 E56.2 E59.4 E62.14 U$9.K1
K7: E64.8 E68.4 E71.1 E74.1 E77.3 E80.13 E81.1 E81.13 E83.6 E84.2 E84.6 K2A3.1 K2B3.1 U$12.K2
K8: E66.6 E68.1 E71.9 E74.6 E77.2 E80.4 E83.14 U$12.K1
K9: E85.8 E89.4 E92.1 E95.1 E98.3 E101.13 E102.1 E102.13 E104.6 E105.2 E105.6 K2A4.1 K2B4.1 U$15.K2
K10: E87.6 E89.1 E92.9 E95.6 E98.2 E101.4 E104.14 U$15.K1
K11: E106.8 E110.4 E113.1 E116.1 E119.3 E122.13 E123.1 E123.13 E125.6 E126.2 E126.6 K2A5.1 K2B5.1 U$18.K2
K12: E108.6 E110.1 E113.9 E116.6 E119.2 E122.4 E125.14 U$18.K1
L1: E2.5 E6.1 E8.2 E11.8 E17.5 E20.12 U$1.L1
L2: E2.4 E5.10 E8.5 E11.2 E14.2 E17.11 E20.5 U$1.L2
L3: E24.10 E26.5 E29.2 E32.2 E35.4 E38.11 E41.5 U$6.L2
L4: E23.1 E26.2 E29.8 E35.5 E38.5 E41.12 U$6.L1
L5: E45.10 E47.5 E50.2 E53.2 E56.4 E59.11 E62.5 U$9.L2
L6: E44.1 E47.2 E50.8 E56.5 E59.5 E62.12 U$9.L1
L7: E66.10 E68.5 E71.2 E74.2 E77.4 E80.11 E83.5 U$12.L2
L8: E65.1 E68.2 E71.8 E77.5 E80.5 E83.12 U$12.L1
L9: E87.10 E89.5 E92.2 E95.2 E98.4 E101.11 E104.5 U$15.L2
L10: E86.1 E89.2 E92.8 E98.5 E101.5 E104.12 U$15.L1
L11: E108.10 E110.5 E113.2 E116.2 E119.4 E122.11 E125.5 U$18.L2
L12: E107.1 E110.2 E113.8 E119.5 E122.5 E125.12 U$18.L1
M1: E2.6 E6.2 E8.13 E12.13 E15.12 E17.6 E20.13 U$1.M1
M2: E2.9 E5.9 E8.6 E11.4 E14.3 E17.12 E20.10 U$1.M2
M3: E24.9 E26.6 E29.4 E32.3 E35.9 E38.12 E41.10 U$6.M2
M4: E23.2 E26.13 E30.13 E33.12 E35.6 E38.6 E41.13 U$6.M1
M5: E45.9 E47.6 E50.4 E53.3 E56.9 E59.12 E62.10 U$9.M2
M6: E44.2 E47.13 E51.13 E54.12 E56.6 E59.6 E62.13 U$9.M1
M7: E66.9 E68.6 E71.4 E74.3 E77.9 E80.12 E83.10 U$12.M2
M8: E65.2 E68.13 E72.13 E75.12 E77.6 E80.6 E83.13 U$12.M1
M9: E87.9 E89.6 E92.4 E95.3 E98.9 E101.12 E104.10 U$15.M2
M10: E86.2 E89.13 E93.13 E96.12 E98.6 E101.6 E104.13 U$15.M1
M11: E108.9 E110.6 E113.4 E116.3 E119.9 E122.12 E125.10 U$18.M2
M12: E107.2 E110.13 E114.13 E117.12 E119.6 E122.6 E125.13 U$18.M1
N1: E3.1 E6.3 E8.12 E12.12 E15.11 E18.3 E21.1 U$1.N1
N2: E2.8 E5.8 E8.11 E11.5 E14.4 E17.10 E20.7 U$1.N2
N3: E24.8 E26.11 E29.5 E32.4 E35.8 E38.10 E41.7 U$6.N2
N4: E23.3 E26.12 E30.12 E33.11 E36.1 E39.3 E42.1 U$6.N1
N5: E45.8 E47.11 E50.5 E53.4 E56.8 E59.10 E62.7 U$9.N2
N6: E44.3 E47.12 E51.12 E54.11 E57.1 E60.3 E63.1 U$9.N1
N7: E66.8 E68.11 E71.5 E74.4 E77.8 E80.10 E83.7 U$12.N2
N8: E65.3 E68.12 E72.12 E75.11 E78.1 E81.3 E84.1 U$12.N1
N9: E87.8 E89.11 E92.5 E95.4 E98.8 E101.10 E104.7 U$15.N2
N10: E86.3 E89.12 E93.12 E96.11 E99.1 E102.3 E105.1 U$15.N1
N11: E108.8 E110.11 E113.5 E116.4 E119.8 E122.10 E125.7 U$18.N2
N12: E107.3 E110.12 E114.12 E117.11 E120.1 E123.3 E126.1 U$18.N1
P1: E3.2 E6.4 E9.1 E12.10 E15.5 E18.2 E21.3 U$1.P1
P2: E3.3 E6.13 E8.10 E11.6 E14.8 E17.9 E20.9 U$1.P2
P3: E23.13 E26.10 E29.6 E32.8 E36.3 E38.9 E41.9 U$6.P2
P4: E23.4 E27.1 E30.10 E33.5 E36.2 E39.2 E42.3 U$6.P1
P5: E44.13 E47.10 E50.6 E53.8 E57.3 E59.9 E62.9 U$9.P2
P6: E44.4 E48.1 E51.10 E54.5 E57.2 E60.2 E63.3 U$9.P1
P7: E65.13 E68.10 E71.6 E74.8 E78.3 E80.9 E83.9 U$12.P2
P8: E65.4 E69.1 E72.10 E75.5 E78.2 E81.2 E84.3 U$12.P1
P9: E86.13 E89.10 E92.6 E95.8 E99.3 E101.9 E104.9 U$15.P2
P10: E86.4 E90.1 E93.10 E96.5 E99.2 E102.2 E105.3 U$15.P1
P11: E107.13 E110.10 E113.6 E116.8 E120.3 E122.9 E125.9 U$18.P2
P12: E107.4 E111.1 E114.10 E117.5 E120.2 E123.2 E126.3 U$18.P1
R1: E3.5 E6.5 E9.2 E12.9 E15.6 E18.4 E21.14 U$1.R1
R2: E3.4 E6.12 E8.9 E12.1 E15.1 E17.8 E20.8 U$1.R2
R3: E23.12 E26.9 E30.1 E33.1 E36.4 E38.8 E41.8 U$6.R2
R4: E23.5 E27.2 E30.9 E33.6 E36.5 E39.4 E42.14 U$6.R1
R5: E44.12 E47.9 E51.1 E54.1 E57.4 E59.8 E62.8 U$9.R2
R6: E44.5 E48.2 E51.9 E54.6 E57.5 E60.4 E63.14 U$9.R1
R7: E65.12 E68.9 E72.1 E75.1 E78.4 E80.8 E83.8 U$12.R2
R8: E65.5 E69.2 E72.9 E75.6 E78.5 E81.4 E84.14 U$12.R1
R9: E86.12 E89.9 E93.1 E96.1 E99.4 E101.8 E104.8 U$15.R2
R10: E86.5 E90.2 E93.9 E96.6 E99.5 E102.4 E105.14 U$15.R1
R11: E107.12 E110.9 E114.1 E117.1 E120.4 E122.8 E125.8 U$18.R2
R12: E107.5 E111.2 E114.9 E117.6 E120.5 E123.4 E126.14 U$18.R1
S1: E3.6 E6.6 E9.13 E12.8 E18.5 E21.12 U$1.S1
S2: E3.13 E6.11 E8.8 E12.2 E15.2 E18.11 E21.5 U$1.S2
S3: E23.11 E26.8 E30.2 E33.2 E36.13 E39.11 E42.5 U$6.S2
S4: E23.6 E27.13 E30.8 E36.6 E39.5 E42.12 U$6.S1
S5: E44.11 E47.8 E51.2 E54.2 E57.13 E60.11 E63.5 U$9.S2
S6: E44.6 E48.13 E51.8 E57.6 E60.5 E63.12 U$9.S1
S7: E65.11 E68.8 E72.2 E75.2 E78.13 E81.11 E84.5 U$12.S2
S8: E65.6 E69.13 E72.8 E78.6 E81.5 E84.12 U$12.S1
S9: E86.11 E89.8 E93.2 E96.2 E99.13 E102.11 E105.5 U$15.S2
S10: E86.6 E90.13 E93.8 E99.6 E102.5 E105.12 U$15.S1
S11: E107.11 E110.8 E114.2 E117.2 E120.13 E123.11 E126.5 U$18.S2
S12: E107.6 E111.13 E114.8 E120.6 E123.5 E126.12 U$18.S1
T1: E23.10 E27.3 E30.4 E33.3 E36.12 E39.12 E42.10 U$6.T2
T2: E3.12 E6.10 E9.3 E12.4 E15.3 E18.12 E21.10 U$1.T2
T3: E44.10 E48.3 E51.4 E54.3 E57.12 E60.12 E63.10 U$9.T2
T4: E65.10 E69.3 E72.4 E75.3 E78.12 E81.12 E84.10 U$12.T2
T5: E86.10 E90.3 E93.4 E96.3 E99.12 E102.12 E105.10 U$15.T2
T6: E107.10 E111.3 E114.4 E117.3 E120.12 E123.12 E126.10 U$18.T2
U1: E3.10 E9.12 E18.6 E21.13 R1.2 R2.1 U$1.U1
U2: E3.9 E6.9 E9.4 E12.5 E15.4 E18.10 E21.7 U$1.U2
U3: E23.9 E27.4 E30.5 E33.4 E36.9 E39.10 E42.7 U$6.U2
U4: E27.12 E36.10 E39.6 E42.13 R5.2 R6.1 U$6.U1
U5: E44.9 E48.4 E51.5 E54.4 E57.9 E60.10 E63.7 U$9.U2
U6: E48.12 E57.10 E60.6 E63.13 R9.2 R10.1 U$9.U1
U7: E65.9 E69.4 E72.5 E75.4 E78.9 E81.10 E84.7 U$12.U2
U8: E69.12 E78.10 E81.6 E84.13 R13.2 R14.1 U$12.U1
U9: E86.9 E90.4 E93.5 E96.4 E99.9 E102.10 E105.7 U$15.U2
U10: E90.12 E99.10 E102.6 E105.13 R17.2 R18.1 U$15.U1
U11: E107.9 E111.4 E114.5 E117.4 E120.9 E123.10 E126.7 U$18.U2
U12: E111.12 E120.10 E123.6 E126.13 R21.2 R22.1 U$18.U1
V1: E3.11 E9.6 E18.8 E21.8 R3.2 R4.1 U$1.V1
V2: E3.8 E6.8 E9.5 E12.6 E15.8 E18.9 E21.9 U$1.V2
V3: E27.6 E36.11 E39.8 E42.8 R7.1 R8.2 U$6.V1
V4: E23.8 E27.5 E30.6 E33.8 E36.8 E39.9 E42.9 U$6.V2
V5: E48.6 E57.11 E60.8 E63.8 R11.1 R12.2 U$9.V1
V6: E44.8 E48.5 E51.6 E54.8 E57.8 E60.9 E63.9 U$9.V2
V7: E69.6 E78.11 E81.8 E84.8 R15.1 R16.2 U$12.V1
V8: E65.8 E69.5 E72.6 E75.8 E78.8 E81.9 E84.9 U$12.V2
V9: E90.6 E99.11 E102.8 E105.8 R19.1 R20.2 U$15.V1
V10: E86.8 E90.5 E93.6 E96.8 E99.8 E102.9 E105.9 U$15.V2
V11: E111.6 E120.11 E123.8 E126.8 R23.1 R24.2 U$18.V1
V12: E107.8 E111.5 E114.6 E117.8 E120.8 E123.9 E126.9 U$18.V2
VCC [Power]: C1.1 C2.1 C3.1 C4.1 C5.1 C6.1 C7.1 C8.1 C9.1 C10.1 C11.1 C12.1 C13.1 C14.1 C15.1 C16.1 C17.1 C18.1 C19.1 C20.1 C21.1 E1.14 E2.14 E3.14 E4.14 E5.14 E6.14 E7.14 E8.14 E9.14 E10.14 E11.14 E12.14 E13.14 E14.14 E15.14 E16.14 E17.14 E18.14 E19.4 E20.4 E21.4 R2.2 R4.2 U$1.A2
VCC1 [Power]: C22.1 C23.1 C24.1 C25.1 C26.1 C27.1 C28.1 C29.1 C30.1 C31.1 C32.1 C33.1 C34.1 C35.1 C36.1 C37.1 C38.1 C39.1 C40.1 C41.1 C42.1 E22.14 E23.14 E24.14 E25.14 E26.14 E27.14 E28.14 E29.14 E30.14 E31.14 E32.14 E33.14 E34.14 E35.14 E36.14 E37.14 E38.14 E39.14 E40.4 E41.4 E42.4 R6.2 R7.2 U$6.A2
VCC2 [Power]: C43.1 C44.1 C45.1 C46.1 C47.1 C48.1 C49.1 C50.1 C51.1 C52.1 C53.1 C54.1 C55.1 C56.1 C57.1 C58.1 C59.1 C60.1 C61.1 C62.1 C63.1 E43.14 E44.14 E45.14 E46.14 E47.14 E48.14 E49.14 E50.14 E51.14 E52.14 E53.14 E54.14 E55.14 E56.14 E57.14 E58.14 E59.14 E60.14 E61.4 E62.4 E63.4 R10.2 R11.2 U$9.A2
VCC3 [Power]: C64.1 C65.1 C66.1 C67.1 C68.1 C69.1 C70.1 C71.1 C72.1 C73.1 C74.1 C75.1 C76.1 C77.1 C78.1 C79.1 C80.1 C81.1 C82.1 C83.1 C84.1 E64.14 E65.14 E66.14 E67.14 E68.14 E69.14 E70.14 E71.14 E72.14 E73.14 E74.14 E75.14 E76.14 E77.14 E78.14 E79.14 E80.14 E81.14 E82.4 E83.4 E84.4 R14.2 R15.2 U$12.A2
VCC4 [Power]: C85.1 C86.1 C87.1 C88.1 C89.1 C90.1 C91.1 C92.1 C93.1 C94.1 C95.1 C96.1 C97.1 C98.1 C99.1 C100.1 C101.1 C102.1 C103.1 C104.1 C105.1 E85.14 E86.14 E87.14 E88.14 E89.14 E90.14 E91.14 E92.14 E93.14 E94.14 E95.14 E96.14 E97.14 E98.14 E99.14 E100.14 E101.14 E102.14 E103.4 E104.4 E105.4 R18.2 R19.2 U$15.A2
VCC5 [Power]: C106.1 C107.1 C108.1 C109.1 C110.1 C111.1 C112.1 C113.1 C114.1 C115.1 C116.1 C117.1 C118.1 C119.1 C120.1 C121.1 C122.1 C123.1 C124.1 C125.1 C126.1 E106.14 E107.14 E108.14 E109.14 E110.14 E111.14 E112.14 E113.14 E114.14 E115.14 E116.14 E117.14 E118.14 E119.14 E120.14 E121.14 E122.14 E123.14 E124.4 E125.4 E126.4 R22.2 R23.2 U$18.A2

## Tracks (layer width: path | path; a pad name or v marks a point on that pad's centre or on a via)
A1  (via drill 0.61)
  Top 0.254: J2.1 86.11,55.37 85.09,56.39 85.09,57.91 86.11,58.93 J1.1 | U$1.A1 13.97,3.3 16.51,3.3 16.76,3.05 16.76,2.54 29.21,2.54 31.75,5.08 31.75,8.64 E1.1 32,8.64 v33.02,8.64 | v41.91,8.64 42.93,8.64 E4.1 | v55.88,8.64 56.9,8.64 E7.1 | v62.23,9.91 63.25,9.91 E10.13 | v73.66,11.18 74.68,11.18 E13.12 76.45,11.43 77.22,10.67 77.22,9.65 v78.99,7.87 | v89.41,8.64 89.41,7.62 91.69,7.62 92.46,8.38 92.46,8.64 E16.1 94.23,8.64 94.23,8.13 98.81,8.13 100.08,6.86 v100.58,6.86 | v102.87,10.16 103.89,10.16 E19.2 | v108.97,7.11 108.97,9.65 v109.22,9.91 108.97,10.16 108.97,22.61 109.22,22.86 109.22,23.88 108.97,24.13 108.97,60.96 95.76,60.96 v94.74,59.94
  Bottom 0.254: v33.02,8.64 v41.91,8.64 42.16,8.64 v55.88,8.64 56.13,8.89 56.9,9.65 61.98,9.65 v62.23,9.91 62.48,10.16 63.5,11.18 v73.66,11.18 | v89.41,8.64 89.15,8.38 80.77,8.38 80.26,7.87 v78.99,7.87 | v102.87,10.16 103.12,9.91 v109.22,9.91 | v108.97,7.11 108.46,7.62 103.89,7.62 103.12,6.86 v100.58,6.86 | v94.74,59.94 87.12,59.94 J1.1
A2  (via drill 0.61)
  Top 0.254: J4.1 86.11,121.41 85.09,122.43 85.09,123.95 86.11,124.97 J3.1 | U$6.A1 13.97,69.34 16.51,69.34 16.76,69.09 16.76,68.58 29.21,68.58 31.75,71.12 31.75,74.68 E34.1 32,74.68 v33.02,74.68 | v41.91,74.68 42.93,74.68 E22.1 | v55.88,74.68 56.9,74.68 E25.1 | v62.23,75.95 63.25,75.95 E28.13 | v73.66,77.22 74.68,77.22 E31.12 76.45,77.47 77.22,76.71 77.22,75.69 v78.99,73.91 | v89.41,74.68 89.41,73.66 91.69,73.66 92.46,74.42 92.46,74.68 E37.1 94.23,74.68 94.23,74.17 98.81,74.17 100.08,72.9 v100.58,72.9 | v102.87,76.2 103.89,76.2 E40.2 | v108.97,73.15 108.97,75.69 v109.22,75.95 108.97,76.2 108.97,88.65 109.22,88.9 109.22,89.92 108.97,90.17 108.97,127 95.76,127 v94.74,125.98
  Bottom 0.254: v33.02,74.68 v41.91,74.68 42.16,74.68 v55.88,74.68 56.13,74.93 56.9,75.69 61.98,75.69 v62.23,75.95 62.48,76.2 63.5,77.22 v73.66,77.22 | v89.41,74.68 89.15,74.42 80.77,74.42 80.26,73.91 v78.99,73.91 | v102.87,76.2 103.12,75.95 v109.22,75.95 | v108.97,73.15 108.46,73.66 103.89,73.66 103.12,72.9 v100.58,72.9 | v94.74,125.98 87.12,125.98 J3.1
A3  (via drill 0.61)
  Top 0.254: J6.1 86.11,187.45 85.09,188.47 85.09,189.99 86.11,191.01 J5.1 | U$9.A1 13.97,135.38 16.51,135.38 16.76,135.13 16.76,134.62 29.21,134.62 31.75,137.16 31.75,140.72 E55.1 32,140.72 v33.02,140.72 | v41.91,140.72 42.93,140.72 E43.1 | v55.88,140.72 56.9,140.72 E46.1 | v62.23,141.99 63.25,141.99 E49.13 | v73.66,143.26 74.68,143.26 E52.12 76.45,143.51 77.22,142.75 77.22,141.73 v78.99,139.95 | v89.41,140.72 89.41,139.7 91.69,139.7 92.46,140.46 92.46,140.72 E58.1 94.23,140.72 94.23,140.21 98.81,140.21 100.08,138.94 v100.58,138.94 | v102.87,142.24 103.89,142.24 E61.2 | v108.97,139.19 108.97,141.73 v109.22,141.99 108.97,142.24 108.97,154.69 109.22,154.94 109.22,155.96 108.97,156.21 108.97,193.04 95.76,193.04 v94.74,192.02
  Bottom 0.254: v33.02,140.72 v41.91,140.72 42.16,140.72 v55.88,140.72 56.13,140.97 56.9,141.73 61.98,141.73 v62.23,141.99 62.48,142.24 63.5,143.26 v73.66,143.26 | v89.41,140.72 89.15,140.46 80.77,140.46 80.26,139.95 v78.99,139.95 | v102.87,142.24 103.12,141.99 v109.22,141.99 | v108.97,139.19 108.46,139.7 103.89,139.7 103.12,138.94 v100.58,138.94 | v94.74,192.02 87.12,192.02 J5.1
A4  (via drill 0.61)
  Top 0.254: J8.1 170.43,138.94 171.45,137.92 171.45,136.4 170.43,135.38 J7.1 | U$12.A1 242.57,191.01 240.03,191.01 239.78,191.26 239.78,191.77 227.33,191.77 224.79,189.23 224.79,185.67 E76.1 224.54,185.67 v223.52,185.67 | v214.63,185.67 213.61,185.67 E64.1 | v200.66,185.67 199.64,185.67 E67.1 | v194.31,184.4 193.29,184.4 E70.13 | v182.88,183.13 181.86,183.13 E73.12 180.09,182.88 179.32,183.64 179.32,184.66 v177.55,186.44 | v167.13,185.67 167.13,186.69 164.85,186.69 164.08,185.93 164.08,185.67 E79.1 162.31,185.67 162.31,186.18 157.73,186.18 156.46,187.45 v155.96,187.45 | v153.67,184.15 152.65,184.15 E82.2 | v147.57,187.2 147.57,184.66 v147.32,184.4 147.57,184.15 147.57,171.7 147.32,171.45 147.32,170.43 147.57,170.18 147.57,133.35 160.78,133.35 v161.8,134.37
  Bottom 0.254: v223.52,185.67 v214.63,185.67 214.38,185.67 v200.66,185.67 200.41,185.42 199.64,184.66 194.56,184.66 v194.31,184.4 194.06,184.15 193.04,183.13 v182.88,183.13 | v167.13,185.67 167.39,185.93 175.77,185.93 176.28,186.44 v177.55,186.44 | v153.67,184.15 153.42,184.4 v147.32,184.4 | v147.57,187.2 148.08,186.69 152.65,186.69 153.42,187.45 v155.96,187.45 | v161.8,134.37 169.42,134.37 J7.1
A5  (via drill 0.61)
  Top 0.254: J10.1 170.43,72.9 171.45,71.88 171.45,70.36 170.43,69.34 J9.1 | U$15.A1 242.57,124.97 240.03,124.97 239.78,125.22 239.78,125.73 227.33,125.73 224.79,123.19 224.79,119.63 E97.1 224.54,119.63 v223.52,119.63 | v214.63,119.63 213.61,119.63 E85.1 | v200.66,119.63 199.64,119.63 E88.1 | v194.31,118.36 193.29,118.36 E91.13 | v182.88,117.09 181.86,117.09 E94.12 180.09,116.84 179.32,117.6 179.32,118.62 v177.55,120.4 | v167.13,119.63 167.13,120.65 164.85,120.65 164.08,119.89 164.08,119.63 E100.1 162.31,119.63 162.31,120.14 157.73,120.14 156.46,121.41 v155.96,121.41 | v153.67,118.11 152.65,118.11 E103.2 | v147.57,121.16 147.57,118.62 v147.32,118.36 147.57,118.11 147.57,105.66 147.32,105.41 147.32,104.39 147.57,104.14 147.57,67.31 160.78,67.31 v161.8,68.33
  Bottom 0.254: v223.52,119.63 v214.63,119.63 214.38,119.63 v200.66,119.63 200.41,119.38 199.64,118.62 194.56,118.62 v194.31,118.36 194.06,118.11 193.04,117.09 v182.88,117.09 | v167.13,119.63 167.39,119.89 175.77,119.89 176.28,120.4 v177.55,120.4 | v153.67,118.11 153.42,118.36 v147.32,118.36 | v147.57,121.16 148.08,120.65 152.65,120.65 153.42,121.41 v155.96,121.41 | v161.8,68.33 169.42,68.33 J9.1
A6  (via drill 0.61)
  Top 0.254: J12.1 170.43,6.86 171.45,5.84 171.45,4.32 170.43,3.3 J11.1 | U$18.A1 242.57,58.93 240.03,58.93 239.78,59.18 239.78,59.69 227.33,59.69 224.79,57.15 224.79,53.59 E118.1 224.54,53.59 v223.52,53.59 | v214.63,53.59 213.61,53.59 E106.1 | v200.66,53.59 199.64,53.59 E109.1 | v194.31,52.32 193.29,52.32 E112.13 | v182.88,51.05 181.86,51.05 E115.12 180.09,50.8 179.32,51.56 179.32,52.58 v177.55,54.36 | v167.13,53.59 167.13,54.61 164.85,54.61 164.08,53.85 164.08,53.59 E121.1 162.31,53.59 162.31,54.1 157.73,54.1 156.46,55.37 v155.96,55.37 | v153.67,52.07 152.65,52.07 E124.2 | v147.57,55.12 147.57,52.58 v147.32,52.32 147.57,52.07 147.57,39.62 147.32,39.37 147.32,38.35 147.57,38.1 147.57,1.27 160.78,1.27 v161.8,2.29
  Bottom 0.254: v223.52,53.59 v214.63,53.59 214.38,53.59 v200.66,53.59 200.41,53.34 199.64,52.58 194.56,52.58 v194.31,52.32 194.06,52.07 193.04,51.05 v182.88,51.05 | v167.13,53.59 167.39,53.85 175.77,53.85 176.28,54.36 v177.55,54.36 | v153.67,52.07 153.42,52.32 v147.32,52.32 | v147.57,55.12 148.08,54.61 152.65,54.61 153.42,55.37 v155.96,55.37 | v161.8,2.29 169.42,2.29 J11.1
B1  (via drill 0.61)
  Top 0.254: v102.87,8.89 103.89,8.89 E19.1 | v91.44,9.91 91.69,10.16 91.69,10.67 92.2,11.18 | 92.2,11.18 92.46,11.43 E16.3 | v91.44,11.94 92.2,11.18 | E13.11 76.45,12.95 77.47,12.95 v77.47,13.21 77.47,13.46 v77.47,17.27 | 46.99,5.08 46.99,7.87 44.7,10.16 E4.2 | 46.99,5.08 46.99,1.02 41.91,1.02 36.07,6.86 36.07,9.91 32,9.91 E1.2 30.23,10.16 28.7,8.64 28.7,7.37 28.96,7.11 28.96,3.05 24.13,3.05 19.3,7.87 19.3,8.38 16,8.38 15.75,8.13 13.97,8.13 U$1.B1 | 46.99,5.08 52.32,5.08 53.34,6.1 53.34,9.91 v55.88,9.91 56.9,9.91 E7.2 | E10.12 63.25,11.18 v62.23,11.18 62.23,11.43 v62.23,15.24
  Bottom 0.254: v102.87,8.89 102.36,9.4 91.95,9.4 v91.44,9.91 | v77.47,13.21 90.17,13.21 v91.44,11.94 | v62.23,11.18 61.21,10.16 56.13,10.16 v55.88,9.91 | v77.47,17.27 64.26,17.27 v62.23,15.24
B4  (via drill 0.61)
  Top 0.254: v102.87,74.93 103.89,74.93 E40.1 | v91.44,75.95 91.69,76.2 91.69,76.71 92.2,77.22 | 92.2,77.22 92.46,77.47 E37.3 | v91.44,77.98 92.2,77.22 | E31.11 76.45,78.99 77.47,78.99 v77.47,79.25 77.47,79.5 v77.47,83.31 | 46.99,71.12 46.99,73.91 44.7,76.2 E22.2 | 46.99,71.12 46.99,67.06 41.91,67.06 36.07,72.9 36.07,75.95 32,75.95 E34.2 30.23,76.2 28.7,74.68 28.7,73.41 28.96,73.15 28.96,69.09 24.13,69.09 19.3,73.91 19.3,74.42 16,74.42 15.75,74.17 13.97,74.17 U$6.B1 | 46.99,71.12 52.32,71.12 53.34,72.14 53.34,75.95 v55.88,75.95 56.9,75.95 E25.2 | E28.12 63.25,77.22 v62.23,77.22 62.23,77.47 v62.23,81.28
  Bottom 0.254: v102.87,74.93 102.36,75.44 91.95,75.44 v91.44,75.95 | v77.47,79.25 90.17,79.25 v91.44,77.98 | v62.23,77.22 61.21,76.2 56.13,76.2 v55.88,75.95 | v77.47,83.31 64.26,83.31 v62.23,81.28
B6  (via drill 0.61)
  Top 0.254: v102.87,140.97 103.89,140.97 E61.1 | v91.44,141.99 91.69,142.24 91.69,142.75 92.2,143.26 | 92.2,143.26 92.46,143.51 E58.3 | v91.44,144.02 92.2,143.26 | E52.11 76.45,145.03 77.47,145.03 v77.47,145.29 77.47,145.54 v77.47,149.35 | 46.99,137.16 46.99,139.95 44.7,142.24 E43.2 | 46.99,137.16 46.99,133.1 41.91,133.1 36.07,138.94 36.07,141.99 32,141.99 E55.2 30.23,142.24 28.7,140.72 28.7,139.45 28.96,139.19 28.96,135.13 24.13,135.13 19.3,139.95 19.3,140.46 16,140.46 15.75,140.21 13.97,140.21 U$9.B1 | 46.99,137.16 52.32,137.16 53.34,138.18 53.34,141.99 v55.88,141.99 56.9,141.99 E46.2 | E49.12 63.25,143.26 v62.23,143.26 62.23,143.51 v62.23,147.32
  Bottom 0.254: v102.87,140.97 102.36,141.48 91.95,141.48 v91.44,141.99 | v77.47,145.29 90.17,145.29 v91.44,144.02 | v62.23,143.26 61.21,142.24 56.13,142.24 v55.88,141.99 | v77.47,149.35 64.26,149.35 v62.23,147.32
B8  (via drill 0.61)
  Top 0.254: v153.67,185.42 152.65,185.42 E82.1 | v165.1,184.4 164.85,184.15 164.85,183.64 164.34,183.13 | 164.34,183.13 164.08,182.88 E79.3 | 164.34,183.13 v165.1,182.37 | E73.11 180.09,181.36 179.07,181.36 v179.07,181.1 179.07,180.85 v179.07,177.04 | 209.55,189.23 209.55,186.44 211.84,184.15 E64.2 | 209.55,189.23 209.55,193.29 214.63,193.29 220.47,187.45 220.47,184.4 224.54,184.4 E76.2 226.31,184.15 227.84,185.67 227.84,186.94 227.58,187.2 227.58,191.26 232.41,191.26 237.24,186.44 237.24,185.93 240.54,185.93 240.79,186.18 242.57,186.18 U$12.B1 | 209.55,189.23 204.22,189.23 203.2,188.21 203.2,184.4 v200.66,184.4 199.64,184.4 E67.2 | E70.12 193.29,183.13 v194.31,183.13 194.31,182.88 v194.31,179.07
  Bottom 0.254: v153.67,185.42 154.18,184.91 164.59,184.91 v165.1,184.4 | v179.07,181.1 166.37,181.1 v165.1,182.37 | v194.31,183.13 195.33,184.15 200.41,184.15 v200.66,184.4 | v179.07,177.04 192.28,177.04 v194.31,179.07
B10  (via drill 0.61)
  Top 0.254: v153.67,119.38 152.65,119.38 E103.1 | v165.1,118.36 164.85,118.11 164.85,117.6 164.34,117.09 | 164.34,117.09 164.08,116.84 E100.3 | 164.34,117.09 v165.1,116.33 | E94.11 180.09,115.32 179.07,115.32 v179.07,115.06 179.07,114.81 v179.07,111 | 209.55,123.19 209.55,120.4 211.84,118.11 E85.2 | 209.55,123.19 209.55,127.25 214.63,127.25 220.47,121.41 220.47,118.36 224.54,118.36 E97.2 226.31,118.11 227.84,119.63 227.84,120.9 227.58,121.16 227.58,125.22 232.41,125.22 237.24,120.4 237.24,119.89 240.54,119.89 240.79,120.14 242.57,120.14 U$15.B1 | 209.55,123.19 204.22,123.19 203.2,122.17 203.2,118.36 v200.66,118.36 199.64,118.36 E88.2 | E91.12 193.29,117.09 v194.31,117.09 194.31,116.84 v194.31,113.03
  Bottom 0.254: v153.67,119.38 154.18,118.87 164.59,118.87 v165.1,118.36 | v179.07,115.06 166.37,115.06 v165.1,116.33 | v194.31,117.09 195.33,118.11 200.41,118.11 v200.66,118.36 | v179.07,111 192.28,111 v194.31,113.03
B12  (via drill 0.61)
  Top 0.254: v153.67,53.34 152.65,53.34 E124.1 | v165.1,52.32 164.85,52.07 164.85,51.56 164.34,51.05 | 164.34,51.05 164.08,50.8 E121.3 | v165.1,50.29 164.34,51.05 | E115.11 180.09,49.28 179.07,49.28 v179.07,49.02 179.07,48.77 v179.07,44.96 | 209.55,57.15 209.55,54.36 211.84,52.07 E106.2 | 209.55,57.15 209.55,61.21 214.63,61.21 220.47,55.37 220.47,52.32 224.54,52.32 E118.2 226.31,52.07 227.84,53.59 227.84,54.86 227.58,55.12 227.58,59.18 232.41,59.18 237.24,54.36 237.24,53.85 240.54,53.85 240.79,54.1 242.57,54.1 U$18.B1 | 209.55,57.15 204.22,57.15 203.2,56.13 203.2,52.32 v200.66,52.32 199.64,52.32 E109.2 | E112.12 193.29,51.05 v194.31,51.05 194.31,50.8 v194.31,46.99
  Bottom 0.254: v153.67,53.34 154.18,52.83 164.59,52.83 v165.1,52.32 | v179.07,49.02 166.37,49.02 v165.1,50.29 | v194.31,51.05 195.33,52.07 200.41,52.07 v200.66,52.32 | v179.07,44.96 192.28,44.96 v194.31,46.99
C1  (via drill 0.61)
  Top 0.254: v14.99,11.18 13.97,11.18 U$1.C1 | E1.3 30.23,11.18 v29.21,11.18 28.96,11.43 27.94,12.45 v27.94,16.76 | E7.13 50.55,10.16 50.04,10.67 50.04,11.18 44.7,11.18 E4.3 42.93,11.68 41.4,11.68 v41.4,15.49 | v67.31,16.26 67.31,15.24 66.55,14.48 66.55,14.22 65.02,14.22 E10.10 | v78.49,16.26 78.99,15.75 78.99,14.99 79.76,14.22 81.03,14.22 E13.5 | v95.25,10.41 94.23,10.41 E16.2 | v102.87,11.68 103.89,11.68 E19.3
  Bottom 0.254: v14.99,11.18 v29.21,11.18 | v67.31,16.26 v78.49,16.26 78.74,16.51 79.25,17.02 | v95.25,10.41 97.28,12.45 100.58,12.45 101.35,13.21 | 101.35,13.21 101.85,13.72 101.85,16.51 103.38,16.51 104.14,17.27 104.14,19.56 81.79,19.56 79.25,17.02 | 101.35,13.21 v102.87,11.68 | 42.16,16.26 v41.4,15.49 | 42.16,16.26 60.71,16.26 62.48,18.03 76.96,18.03 77.22,18.29 77.98,18.29 79.25,17.02 | v27.94,16.76 28.45,16.26 42.16,16.26
C2  (via drill 0.61)
  Top 0.254: v14.99,77.22 13.97,77.22 U$6.C1 | E34.3 30.23,77.22 v29.21,77.22 28.96,77.47 27.94,78.49 v27.94,82.8 | E25.13 50.55,76.2 50.04,76.71 50.04,77.22 44.7,77.22 E22.3 42.93,77.72 41.4,77.72 v41.4,81.53 | v67.31,82.3 67.31,81.28 66.55,80.52 66.55,80.26 65.02,80.26 E28.10 | v78.49,82.3 78.99,81.79 78.99,81.03 79.76,80.26 81.03,80.26 E31.5 | v95.25,76.45 94.23,76.45 E37.2 | v102.87,77.72 103.89,77.72 E40.3
  Bottom 0.254: v14.99,77.22 v29.21,77.22 | v67.31,82.3 v78.49,82.3 78.74,82.55 79.25,83.06 | v95.25,76.45 97.28,78.49 100.58,78.49 101.35,79.25 | 101.35,79.25 101.85,79.76 101.85,82.55 103.38,82.55 104.14,83.31 104.14,85.6 81.79,85.6 79.25,83.06 | 101.35,79.25 v102.87,77.72 | 42.16,82.3 v41.4,81.53 | 42.16,82.3 60.71,82.3 62.48,84.07 76.96,84.07 77.22,84.33 77.98,84.33 79.25,83.06 | v27.94,82.8 28.45,82.3 42.16,82.3
C3  (via drill 0.61)
  Top 0.254: v14.99,143.26 13.97,143.26 U$9.C1 | E55.3 30.23,143.26 v29.21,143.26 28.96,143.51 27.94,144.53 v27.94,148.84 | E46.13 50.55,142.24 50.04,142.75 50.04,143.26 44.7,143.26 E43.3 42.93,143.76 41.4,143.76 v41.4,147.57 | v67.31,148.34 67.31,147.32 66.55,146.56 66.55,146.3 65.02,146.3 E49.10 | v78.49,148.34 78.99,147.83 78.99,147.07 79.76,146.3 81.03,146.3 E52.5 | v95.25,142.49 94.23,142.49 E58.2 | v102.87,143.76 103.89,143.76 E61.3
  Bottom 0.254: v29.21,143.26 v14.99,143.26 | v67.31,148.34 v78.49,148.34 78.74,148.59 79.25,149.1 | v95.25,142.49 97.28,144.53 100.58,144.53 101.35,145.29 | 101.35,145.29 101.85,145.8 101.85,148.59 103.38,148.59 104.14,149.35 104.14,151.64 81.79,151.64 79.25,149.1 | 101.35,145.29 v102.87,143.76 | 42.16,148.34 v41.4,147.57 | 42.16,148.34 60.71,148.34 62.48,150.11 76.96,150.11 77.22,150.37 77.98,150.37 79.25,149.1 | v27.94,148.84 28.45,148.34 42.16,148.34
C4  (via drill 0.61)
  Top 0.254: v241.55,183.13 242.57,183.13 U$12.C1 | E76.3 226.31,183.13 v227.33,183.13 227.58,182.88 228.6,181.86 v228.6,177.55 | E67.13 205.99,184.15 206.5,183.64 206.5,183.13 211.84,183.13 E64.3 213.61,182.63 215.14,182.63 v215.14,178.82 | v189.23,178.05 189.23,179.07 189.99,179.83 189.99,180.09 191.52,180.09 E70.10 | v178.05,178.05 177.55,178.56 177.55,179.32 176.78,180.09 175.51,180.09 E73.5 | v161.29,183.9 162.31,183.9 E79.2 | v153.67,182.63 152.65,182.63 E82.3
  Bottom 0.254: v227.33,183.13 v241.55,183.13 | v189.23,178.05 v178.05,178.05 177.8,177.8 177.29,177.29 | v161.29,183.9 159.26,181.86 155.96,181.86 155.19,181.1 | 155.19,181.1 154.69,180.59 154.69,177.8 153.16,177.8 152.4,177.04 152.4,174.75 174.75,174.75 177.29,177.29 | 155.19,181.1 v153.67,182.63 | 214.38,178.05 v215.14,178.82 | 214.38,178.05 195.83,178.05 194.06,176.28 179.58,176.28 179.32,176.02 178.56,176.02 177.29,177.29 | v228.6,177.55 228.09,178.05 214.38,178.05
C5  (via drill 0.61)
  Top 0.254: v241.55,117.09 242.57,117.09 U$15.C1 | E97.3 226.31,117.09 v227.33,117.09 227.58,116.84 228.6,115.82 v228.6,111.51 | E88.13 205.99,118.11 206.5,117.6 206.5,117.09 211.84,117.09 E85.3 213.61,116.59 215.14,116.59 v215.14,112.78 | v189.23,112.01 189.23,113.03 189.99,113.79 189.99,114.05 191.52,114.05 E91.10 | v178.05,112.01 177.55,112.52 177.55,113.28 176.78,114.05 175.51,114.05 E94.5 | v161.29,117.86 162.31,117.86 E100.2 | v153.67,116.59 152.65,116.59 E103.3
  Bottom 0.254: v227.33,117.09 v241.55,117.09 | v189.23,112.01 v178.05,112.01 177.8,111.76 177.29,111.25 | v161.29,117.86 159.26,115.82 155.96,115.82 155.19,115.06 | 155.19,115.06 154.69,114.55 154.69,111.76 153.16,111.76 152.4,111 152.4,108.71 174.75,108.71 177.29,111.25 | 155.19,115.06 v153.67,116.59 | 214.38,112.01 v215.14,112.78 | 214.38,112.01 195.83,112.01 194.06,110.24 179.58,110.24 179.32,109.98 178.56,109.98 177.29,111.25 | v228.6,111.51 228.09,112.01 214.38,112.01
C6  (via drill 0.61)
  Top 0.254: v241.55,51.05 242.57,51.05 U$18.C1 | E118.3 226.31,51.05 v227.33,51.05 227.58,50.8 228.6,49.78 v228.6,45.47 | E109.13 205.99,52.07 206.5,51.56 206.5,51.05 211.84,51.05 E106.3 213.61,50.55 215.14,50.55 v215.14,46.74 | v189.23,45.97 189.23,46.99 189.99,47.75 189.99,48.01 191.52,48.01 E112.10 | v178.05,45.97 177.55,46.48 177.55,47.24 176.78,48.01 175.51,48.01 E115.5 | v161.29,51.82 162.31,51.82 E121.2 | v153.67,50.55 152.65,50.55 E124.3
  Bottom 0.254: v227.33,51.05 v241.55,51.05 | v189.23,45.97 v178.05,45.97 177.8,45.72 177.29,45.21 | v161.29,51.82 159.26,49.78 155.96,49.78 155.19,49.02 | 155.19,49.02 154.69,48.51 154.69,45.72 153.16,45.72 152.4,44.96 152.4,42.67 174.75,42.67 177.29,45.21 | 155.19,49.02 v153.67,50.55 | v215.14,46.74 214.38,45.97 | 214.38,45.97 195.83,45.97 194.06,44.2 179.58,44.2 179.32,43.94 178.56,43.94 177.29,45.21 | v228.6,45.47 228.09,45.97 214.38,45.97
D1  (via drill 0.61)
